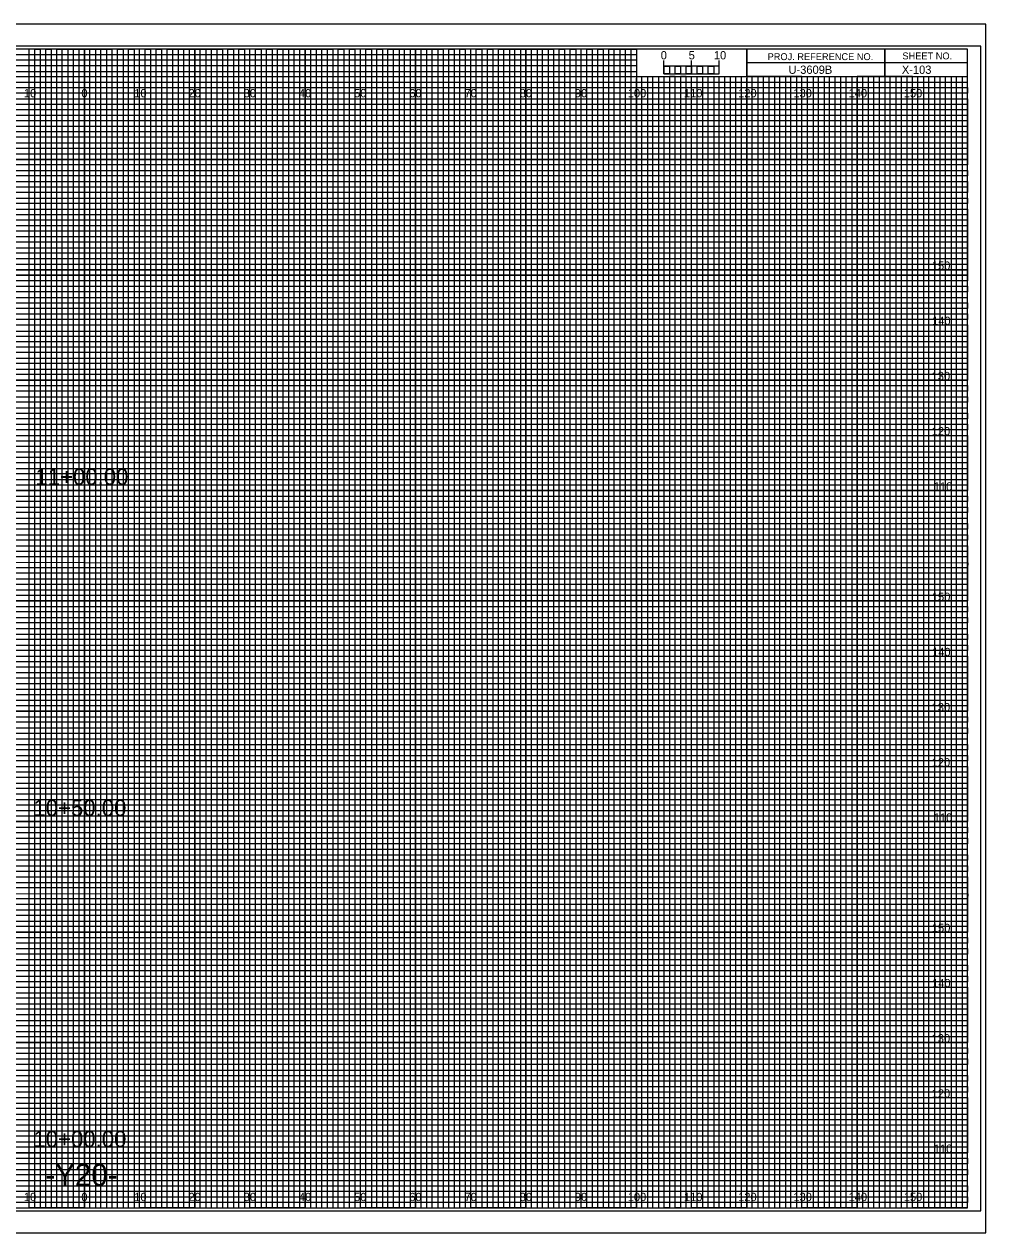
# Model space of a CAD drawing. Extents: x -13 to 323, y -5 to 2634.
# Drawn here: x 149.1 to 323.3, y -4.5 to 214.5 of the extents above; entities that cross this region are included whole.
import ezdxf

# ---------------------------------------------------------------- set-up
doc = ezdxf.new("R2010")
doc.units = 0
for name, color, linetype in [('Exist CMT Pavement', 7, 'Continuous'), ('Exist Cross Section Cell', 7, 'Continuous'), ('Exist XS Center Line Elevation Label', 7, 'Continuous'), ('Exist XS Ground Line', 7, 'Continuous'), ('Prop CMT Pvmt Course 1 Wedge', 7, 'Continuous'), ('Prop CMT Pvmt Course 2', 7, 'Continuous'), ('Prop CMT Pvmt Course 2 Wedge', 7, 'Continuous'), ('Prop CMT Pvmt Course 3', 7, 'Continuous'), ('Prop CMT Pvmt Course 3 Wedge', 7, 'Continuous'), ('Prop CMT Pvmt Surface', 7, 'Continuous'), ('Prop CMT Pvmt Wedge Surface 1', 7, 'Continuous'), ('Prop CMT Pvmt Wedge Surface 2', 7, 'Continuous'), ('Prop CMT Shld Paved Course 1', 7, 'Continuous'), ('Prop CMT Shld Paved Course 2', 7, 'Continuous'), ('Prop CMT Shld Paved Course 3', 7, 'Continuous'), ('Prop CMT Subgrade Earthwork', 7, 'Continuous'), ('Scratch_Level_0', 7, 'Continuous')]:
    doc.layers.add(name, color=color, linetype=linetype)

msp = doc.modelspace()

# ---------------------------------------------------------------- linework, layer by layer
at = {"layer": 'Exist XS Center Line Elevation Label'}
for points in [[(145, 0), (155, 0), (155, 210), (165, 210), (165, 0), (175, 0), (175, 210), (185, 210), (185, 0), (195, 0), (195, 210), (205, 210), (205, 0), (215, 0), (215, 210), (225, 210), (225, 0), (235, 0), (235, 210), (245, 210), (245, 0), (255, 0), (255, 210), (259.93, 210), (260, 210), (260, 205), (264.99, 205), (264.99, 0), (275, 0), (275, 205), (285, 205), (285, 0), (295, 0), (295, 205), (305, 205), (305, 0), (315, 0), (315, 205)], [(0, 205), (275, 205)], [(0, 185), (320, 185), (320, 195), (0, 195)], [(0, 165), (320, 165), (320, 175), (0, 175)], [(0, 145), (320, 145), (320, 155), (0, 155)], [(0, 125), (320, 125), (320, 135), (0, 135)], [(0, 105), (320, 105), (320, 115), (0, 115)], [(0, 85), (320, 85), (320, 95), (0, 95)], [(0, 65), (320, 65), (320, 75), (0, 75)], [(0, 45), (320, 45), (320, 55), (0, 55)], [(0, 25), (320, 25), (320, 35), (0, 35)], [(0, 5), (320, 5), (320, 15), (0, 15)]]:
    msp.add_lwpolyline(points, dxfattribs=at)
at = {"layer": 'Exist XS Ground Line'}
for p, q in [((150, 210), (140, 210)), ((150, 0), (150, 210)), ((170, 210), (160, 210)), ((160, 210), (160, 0)), ((170, 0), (170, 210)), ((190, 210), (180, 210)), ((180, 210), (180, 0)), ((190, 0), (190, 210)), ((210, 210), (200, 210)), ((200, 210), (200, 0)), ((210, 0), (210, 210)), ((230, 210), (220, 210)), ((220, 210), (220, 0)), ((230, 0), (230, 210)), ((250, 210), (240, 210)), ((240, 210), (240, 0)), ((250, 0), (250, 210)), ((260, 210), (260, 0)), ((270, 0), (270, 205)), ((290, 205), (280, 205)), ((280, 205), (280, 0)), ((290, 0), (290, 205)), ((310, 205), (300, 205)), ((300, 205), (300, 0)), ((310, 0), (310, 205)), ((160, 0), (150, 0)), ((180, 0), (170, 0)), ((200, 0), (190, 0)), ((220, 0), (210, 0)), ((240, 0), (230, 0)), ((260, 0), (250, 0)), ((280, 0), (270, 0)), ((300, 0), (290, 0)), ((320, 0), (310, 0)), ((320, 0), (320, 0))]:
    msp.add_line(p, q, dxfattribs=at)
for points in [[(0, 200), (320, 200), (320, 190), (0, 190)], [(0, 180), (320, 180), (320, 170), (0, 170)], [(0, 160), (320, 160), (320, 150), (0, 150)], [(0, 140), (320, 140), (320, 130), (0, 130)], [(0, 120), (320, 120), (320, 110), (0, 110)], [(0, 100), (320, 100), (320, 90), (0, 90)], [(0, 80), (320, 80), (320, 70), (0, 70)], [(0, 60), (320, 60), (320, 50), (0, 50)], [(0, 40), (320, 40), (320, 30), (0, 30)], [(0, 20), (320, 20), (320, 10), (0, 10)]]:
    msp.add_lwpolyline(points, dxfattribs=at)
at = {"layer": 'Prop CMT Pvmt Course 1 Wedge'}
for p, q in [((323.3, 214.5), (-13.4, 214.5)), ((-13.4, -4.5), (323.3, -4.5))]:
    msp.add_line(p, q, dxfattribs=at)
at = {"layer": 'Prop CMT Pvmt Course 2'}
msp.add_lwpolyline([(-13.4, -4.5), (323.3, -4.5), (323.3, 214.5), (-13.4, 214.5)], close=True, dxfattribs=at)
at = {"layer": 'Prop CMT Pvmt Course 3'}
msp.add_lwpolyline([(-10.8, -0.5), (322.4, -0.5), (322.4, 210.5), (-10.8, 210.5)], close=True, dxfattribs=at)
at = {"layer": 'Prop CMT Shld Paved Course 1'}
for p, q in [((305, 210), (305, 205)), ((305, 205), (305, 210)), ((280, 207.5), (280, 205)), ((320, 207.49), (280, 207.49)), ((280, 205), (320, 205))]:
    msp.add_line(p, q, dxfattribs=at)
for points in [[(320, 210), (0, 210), (0, 0), (320, 0)], [(280, 210), (260, 210), (260, 205.03), (280, 205.03)], [(320, 210), (280, 210), (280, 205), (320, 205)]]:
    msp.add_lwpolyline(points, close=True, dxfattribs=at)
at = {"layer": 'Prop CMT Shld Paved Course 2'}
for p, q in [((267, 205), (266.01, 205)), ((266.01, 205), (266.01, 0)), ((267, 0), (267, 205)), ((269, 205), (268, 205)), ((268, 205), (268, 0)), ((269, 0), (269, 205)), ((266.01, 0), (265, 0)), ((268, 0), (267, 0))]:
    msp.add_line(p, q, dxfattribs=at)
for points in [[(150, 0), (151, 0), (151, 210), (152, 210), (152, 0)], [(152, 0), (153, 0), (153, 210), (154, 210), (154, 0)], [(155, 0), (156, 0), (156, 210), (157, 210), (157, 0)], [(157, 0), (158, 0), (158, 210), (159, 210), (159, 0)], [(160, 0), (161, 0), (161, 210), (162, 210), (162, 0)], [(162, 0), (163, 0), (163, 210), (164, 210), (164, 0)], [(165, 0), (166, 0), (166, 210), (167, 210), (167, 0)], [(167, 0), (168, 0), (168, 210), (169, 210), (169, 0)], [(170, 0), (171, 0), (171, 210), (172, 210), (172, 0)], [(172, 0), (173, 0), (173, 210), (174, 210), (174, 0)], [(175, 0), (176, 0), (176, 210), (177, 210), (177, 0)], [(177, 0), (178, 0), (178, 210), (179, 210), (179, 0)], [(180, 0), (181, 0), (181, 210), (182, 210), (182, 0)], [(182, 0), (183, 0), (183, 210), (184, 210), (184, 0)], [(185, 0), (186, 0), (186, 210), (187, 210), (187, 0)], [(187, 0), (188, 0), (188, 210), (189, 210), (189, 0)], [(190, 0), (191, 0), (191, 210), (192, 210), (192, 0)], [(192, 0), (193, 0), (193, 210), (194, 210), (194, 0)], [(195, 0), (196, 0), (196, 210), (197, 210), (197, 0)], [(197, 0), (198, 0), (198, 210), (199, 210), (199, 0)], [(200, 0), (201, 0), (201, 210), (202, 210), (202, 0)], [(202, 0), (203, 0), (203, 210), (204, 210), (204, 0)], [(205, 0), (206, 0), (206, 210), (207, 210), (207, 0)], [(207, 0), (208, 0), (208, 210), (209, 210), (209, 0)], [(210, 0), (211, 0), (211, 210), (212, 210), (212, 0)], [(212, 0), (213, 0), (213, 210), (214, 210), (214, 0)], [(215, 0), (216, 0), (216, 210), (217, 210), (217, 0)], [(217, 0), (218, 0), (218, 210), (219, 210), (219, 0)], [(220, 0), (221, 0), (221, 210), (222, 210), (222, 0)], [(222, 0), (223, 0), (223, 210), (224, 210), (224, 0)], [(225, 0), (226, 0), (226, 210), (227, 210), (227, 0)], [(227, 0), (228, 0), (228, 210), (229, 210), (229, 0)], [(230, 0), (231, 0), (231, 210), (232, 210), (232, 0)], [(232, 0), (233, 0), (233, 210), (234, 210), (234, 0)], [(235, 0), (236, 0), (236, 210), (237, 210), (237, 0)], [(237, 0), (238, 0), (238, 210), (239, 210), (239, 0)], [(240, 0), (241, 0), (241, 210), (242, 210), (242, 0)], [(242, 0), (243, 0), (243, 210), (244, 210), (244, 0)], [(245, 0), (246, 0), (246, 210), (247, 210), (247, 0)], [(247, 0), (248, 0), (248, 210), (249, 210), (249, 0)], [(250, 0), (251, 0), (251, 210), (252, 210), (252, 0)], [(252, 0), (253, 0), (253, 210), (254, 210), (254, 0)], [(255, 0), (256, 0), (256, 210), (257, 210), (257, 0)], [(257, 0), (258, 0), (258, 210), (259, 210), (259, 0)], [(260, 0), (261, 0), (261, 205), (262.02, 205), (262.02, 0)], [(262, 0), (263, 0), (263, 205), (263.99, 205), (263.99, 0)], [(270, 0), (270.98, 0), (270.98, 205), (272, 205), (272, 0)], [(272, 0), (273, 0), (273, 205), (274.05, 205), (274.05, 0)], [(275, 0), (276, 0), (276, 205), (277, 205), (277, 0)], [(277, 0), (278, 0), (278, 205), (279, 205), (279, 0)], [(280, 0), (281, 0), (281, 205), (282, 205), (282, 0)], [(282, 0), (283, 0), (283, 205), (284, 205), (284, 0)], [(285, 0), (286, 0), (286, 205), (287, 205), (287, 0)], [(287, 0), (288, 0), (288, 205), (289, 205), (289, 0)], [(290, 0), (291, 0), (291, 205), (292, 205), (292, 0)], [(292, 0), (293, 0), (293, 205), (294, 205), (294, 0)], [(295, 0), (296, 0), (296, 205), (297, 205), (297, 0)], [(297, 0), (298, 0), (298, 205), (299, 205), (299, 0)], [(300, 0), (301, 0), (301, 205), (302, 205), (302, 0)], [(302, 0), (303, 0), (303, 205), (304, 205), (304, 0)], [(305, 0), (306, 0), (306, 205), (307, 205), (307, 0)], [(307, 0), (308, 0), (308, 205), (309, 205), (309, 0)], [(310, 0), (311, 0), (311, 205), (312, 205), (312, 0)], [(312, 0), (313, 0), (313, 205), (314, 205), (314, 0)], [(315, 0), (316, 0), (316, 205), (317, 205), (317, 0)], [(317, 0), (318, 0), (318, 205), (319, 205), (319, 0)]]:
    msp.add_lwpolyline(points, dxfattribs=at)
at = {"layer": 'Prop CMT Shld Paved Course 3'}
for p, q in [((265, 205.49), (265, 207.9)), ((265, 206.9), (265, 207.9)), ((270, 205.49), (270, 207.9)), ((275, 205.49), (275, 207.9)), ((275, 206.9), (275, 207.9))]:
    msp.add_line(p, q, dxfattribs=at)
for points in [[(275, 206.9), (265, 206.9), (265, 205.49), (275, 205.49)], [(265, 206.9), (266, 206.9), (266, 205.49), (265, 205.49)], [(267, 206.9), (268, 206.9), (268, 205.49), (267, 205.49)], [(269, 206.9), (270, 206.9), (270, 205.49), (269, 205.49)], [(271, 206.9), (272, 206.9), (272, 205.49), (271, 205.49)], [(273, 206.9), (274, 206.9), (274, 205.49), (273, 205.49)]]:
    msp.add_lwpolyline(points, close=True, dxfattribs=at)
at = {"layer": 'Prop CMT Subgrade Earthwork'}
for p, q in [((150, 0), (150, 210)), ((160, 0), (160, 210)), ((170, 0), (170, 210)), ((180, 0), (180, 210)), ((190, 0), (190, 210)), ((200, 0), (200, 210)), ((210, 0), (210, 210)), ((220, 0), (220, 210)), ((230, 0), (230, 210)), ((240, 0), (240, 210)), ((250, 0), (250, 210)), ((260, 0), (260, 204.69)), ((270, 0), (270, 204.69)), ((280, 0), (280, 204.69)), ((290, 0), (290, 204.69)), ((300, 0), (300, 204.69)), ((310, 0), (310, 204.69)), ((0, 200), (320, 200)), ((0, 190), (320, 190)), ((0, 180), (320, 180)), ((0, 170), (320, 170)), ((0, 160), (320, 160)), ((0, 150), (320, 150)), ((0, 140), (320, 140)), ((0, 130), (320, 130)), ((0, 120), (320, 120)), ((0, 110), (320, 110)), ((0, 100), (320, 100)), ((0, 90), (320, 90)), ((0, 80), (320, 80)), ((0, 70), (320, 70)), ((0, 60), (320, 60)), ((0, 50), (320, 50)), ((0, 40), (320, 40)), ((0, 30), (320, 30)), ((0, 20), (320, 20)), ((0, 10), (320, 10))]:
    msp.add_line(p, q, dxfattribs=at)
at = {"layer": 'Scratch_Level_0'}
for p, q in [((0, 209), (260, 209)), ((260, 209), (260, 207.98)), ((260, 207.98), (0, 207.98)), ((0, 207), (260, 207)), ((260, 205.89), (0, 205.89)), ((260, 207), (260, 205.89)), ((0, 204), (320, 204))]:
    msp.add_line(p, q, dxfattribs=at)
for points in [[(0, 203), (270, 203), (320, 203), (320, 202), (0, 202)], [(0, 201), (320, 201), (320, 199), (0, 199)], [(0, 198), (320, 198), (320, 197), (0, 196.98)], [(0, 196), (320, 196), (320, 194), (0, 194)], [(0, 193), (320, 193), (320, 192), (0, 192)], [(0, 191), (320, 191), (320, 189), (0, 189)], [(0, 188), (320, 188), (320, 187), (0, 187)], [(0, 186), (320, 186), (320, 184), (0, 184)], [(0, 183), (320, 183), (320, 182), (0, 182)], [(0, 181), (320, 181), (320, 179), (0, 179)], [(0, 178), (320, 178), (320, 177), (0, 177)], [(0, 176), (320, 176), (320, 173.95), (320, 173), (320, 172), (0, 172)], [(0, 174), (320, 174), (320, 173), (0, 173)], [(0, 171), (320, 171), (320, 169), (0, 169.03)], [(0, 169.03), (320, 169), (320, 168), (0, 168)], [(0, 167), (320, 167), (320, 166), (0, 166)], [(0, 164), (320, 164), (320, 163), (0, 163)], [(0, 162), (320, 162), (320, 161), (0, 161)], [(-0.07, 158.89), (320, 158.89), (320, 157.88), (-0.07, 157.88)], [(0, 157), (320, 157), (320, 156), (0, 156)], [(0, 154), (320, 154), (320, 153), (0, 153)], [(0, 152), (320, 152), (320, 151), (0, 151)], [(0, 149), (320, 149), (320, 148), (0, 148)], [(0, 147), (320, 147), (320, 146), (0, 146)], [(0, 144), (320, 144), (320, 143), (0, 143)], [(0, 142), (320, 142), (320, 141), (0, 141)], [(0, 139), (320, 139), (319.99, 137.98), (0, 138)], [(0, 137), (320, 137), (320, 136), (0, 136)], [(0, 134), (320, 134), (320, 133), (0, 133)], [(0, 132), (320, 132), (320, 131), (0, 131)], [(0, 129), (320, 129), (320, 128), (0, 128)], [(0, 127), (320, 127), (320, 126), (0, 126)], [(0, 124), (320, 124), (320, 123), (0, 123)], [(0, 122), (320, 122), (320, 121), (0, 121)], [(0, 119), (320, 119), (320, 118), (0, 118)], [(0, 116.99), (320.07, 116.91), (320, 116), (0, 116)], [(0, 114), (320, 114), (320, 113), (0, 113)], [(0, 112), (320, 112), (320, 111), (0, 111)], [(0, 109), (320, 109), (320, 108), (0, 108)], [(0, 107), (320, 107), (320, 106), (0, 106)], [(0, 104), (320, 104), (320, 103), (0, 103)], [(0, 102), (320, 102), (320, 101), (0, 101)], [(0, 99), (320, 99), (320, 98), (0, 98)], [(0, 97), (320, 97), (320, 96), (0, 96)], [(0, 94), (320, 94), (320, 93), (0, 93)], [(0, 92), (320, 92), (320, 91), (0, 91)], [(0, 89), (320, 89), (320, 88), (0, 88)], [(0, 87), (320, 87), (320, 86), (0, 86)], [(0, 84), (320, 84), (320, 83), (0, 83)], [(0, 82), (320, 82), (320, 81), (0, 81)], [(0, 79), (320, 79), (319.99, 77.98), (0, 78)], [(0, 77), (320, 77), (320, 76), (0, 76)], [(0, 74), (320, 74), (320, 73), (0, 73)], [(0, 72), (320, 72), (320, 71), (0, 71)], [(0, 69), (320, 69), (320, 68), (0, 68)], [(0, 67), (320, 67), (320, 66), (0, 66)], [(0, 64), (320, 64), (320, 63), (0, 63)], [(0, 62), (320, 62), (320, 61), (0, 61)], [(0, 59), (320, 59), (320, 58), (0, 58)], [(0, 56.99), (320.07, 56.91), (320, 56), (0, 56)], [(0, 54), (320, 54), (320, 53), (0, 53)], [(0, 52), (320, 52), (320, 51), (0, 51)], [(0, 49), (320, 49), (320, 48), (0, 48)], [(0, 47), (320, 47), (320, 46), (0, 46)], [(0, 44), (320, 44), (320, 43), (0, 43)], [(0, 42), (320, 42), (320, 41), (0, 41)], [(0, 39), (320, 39), (320, 38), (0, 38)], [(0, 37), (320, 37), (320, 36), (0, 36)], [(0, 34), (320, 34), (320, 33), (0, 33)], [(0, 32), (320, 32), (320, 31), (0, 31)], [(0, 29), (320, 29), (320, 28), (0, 28)], [(0, 27), (320, 27), (320, 26), (0, 26)], [(0, 24), (320, 24), (320, 23), (0, 23)], [(0, 22), (320, 22), (320, 21), (0, 21)], [(0, 19), (320, 19), (320, 18), (0, 18)], [(0, 17), (320, 17), (320, 16), (0, 16)], [(0, 14), (320, 14), (320, 13), (0, 13)], [(0, 12), (320, 12), (320, 11), (0, 11)], [(0, 9), (320, 9), (320, 8), (0, 8)], [(0, 7), (320, 7), (320, 6), (0, 6)], [(0, 4), (320, 4), (320, 3), (0, 3)], [(0, 2), (320, 2), (320, 1), (0, 1)]]:
    msp.add_lwpolyline(points, dxfattribs=at)

# ---------------------------------------------------------------- texts
at = {"layer": 'Exist CMT Pavement'}
msp.add_text('X-103', height=1.5, dxfattribs=at).set_placement((308.09, 205.5))
at = {"layer": 'Exist Cross Section Cell'}
for s, p in [('10', (149.04, 201.25)), ('0', (159.45, 201.25)), ('0', (159.45, 201.25)), ('10', (169.04, 201.25)), ('20', (178.86, 201.25)), ('30', (188.86, 201.25)), ('40', (198.86, 201.25)), ('50', (208.86, 201.25)), ('60', (218.86, 201.25)), ('70', (228.86, 201.25)), ('80', (238.86, 201.25)), ('90', (248.86, 201.25)), ('100', (258.44, 201.25)), ('110', (268.62, 201.25)), ('120', (278.44, 201.25)), ('130', (288.44, 201.25)), ('140', (298.44, 201.25)), ('150', (308.44, 201.25)), ('10', (149.04, 1.25)), ('0', (159.45, 1.25)), ('0', (159.45, 1.25)), ('10', (169.04, 1.25)), ('20', (178.86, 1.25)), ('30', (188.86, 1.25)), ('40', (198.86, 1.25)), ('50', (208.86, 1.25)), ('60', (218.86, 1.25)), ('70', (228.86, 1.25)), ('80', (238.86, 1.25)), ('90', (248.86, 1.25)), ('100', (258.44, 1.25)), ('110', (268.62, 1.25)), ('120', (278.44, 1.25)), ('130', (288.44, 1.25)), ('140', (298.44, 1.25)), ('150', (308.44, 1.25))]:
    msp.add_text(s, height=1.5, dxfattribs=at).set_placement(p)
at = {"layer": 'Prop CMT Pvmt Course 2 Wedge'}
for s, p in [('150', (313.52, 170)), ('140', (313.57, 160)), ('130', (313.49, 150)), ('120', (313.5, 140)), ('110', (313.88, 130)), ('150', (313.52, 110)), ('140', (313.57, 100)), ('130', (313.49, 90)), ('120', (313.5, 80)), ('110', (313.88, 70)), ('150', (313.52, 50)), ('140', (313.57, 40)), ('130', (313.49, 30)), ('120', (313.5, 20)), ('110', (313.88, 10))]:
    msp.add_text(s, height=1.5, dxfattribs=at).set_placement(p)
at = {"layer": 'Prop CMT Pvmt Course 3 Wedge'}
for s, p in [('11+00.00', (151.13, 131)), ('10+50.00', (150.77, 71)), ('10+00.00', (150.77, 11))]:
    msp.add_text(s, height=3, dxfattribs=at).set_placement(p)
at = {"layer": 'Prop CMT Pvmt Surface'}
msp.add_text('U-3609B', height=1.5, dxfattribs=at).set_placement((287.56, 205.5))
at = {"layer": 'Prop CMT Pvmt Wedge Surface 1'}
msp.add_text('-Y20-', height=4, dxfattribs=at).set_placement((152.93, 4))
at = {"layer": 'Prop CMT Pvmt Wedge Surface 2'}
for s, p in [('5', (269.47, 208.12)), ('10', (274.04, 208.12))]:
    msp.add_text(s, height=1.5, dxfattribs=at).set_placement(p)
at = {"layer": 'Prop CMT Shld Paved Course 1'}
for s, p in [('PROJ. REFERENCE NO.', (283.77, 207.99)), ('SHEET NO.', (308.19, 208.12))]:
    msp.add_text(s, height=1.25, dxfattribs=at).set_placement(p)
at = {"layer": 'Prop CMT Shld Paved Course 3'}
msp.add_text('0', height=1.5, dxfattribs=at).set_placement((264.41, 208.12))

doc.saveas('drawing.dxf')
